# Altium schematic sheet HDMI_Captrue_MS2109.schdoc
size 297 x 209 mm; Border: 1; Symbol: Drawing-Symbol_A4; Company: 嘉立创EDA; Version: V1.0; Page Size: A4; @Project Name: New Project_2025-01-23_00-40-50; @Page Count: 4; @Update Date: 2025-08-15; @Create Date: 2025-07-30; @Schematic Name: Schematic3_7; @Page No: 4; @Page Name: 采集卡; @Create Time: 15:34:36; @Update Time: 14:29:42; Width: 1170; Height: 825; Region Start: 1; X Region Count: 6; Y Region Count: 4; Blade Width: 10; Title Block Position: 3; @Board Name: cm4; Device: Drawing-Symbol_A4
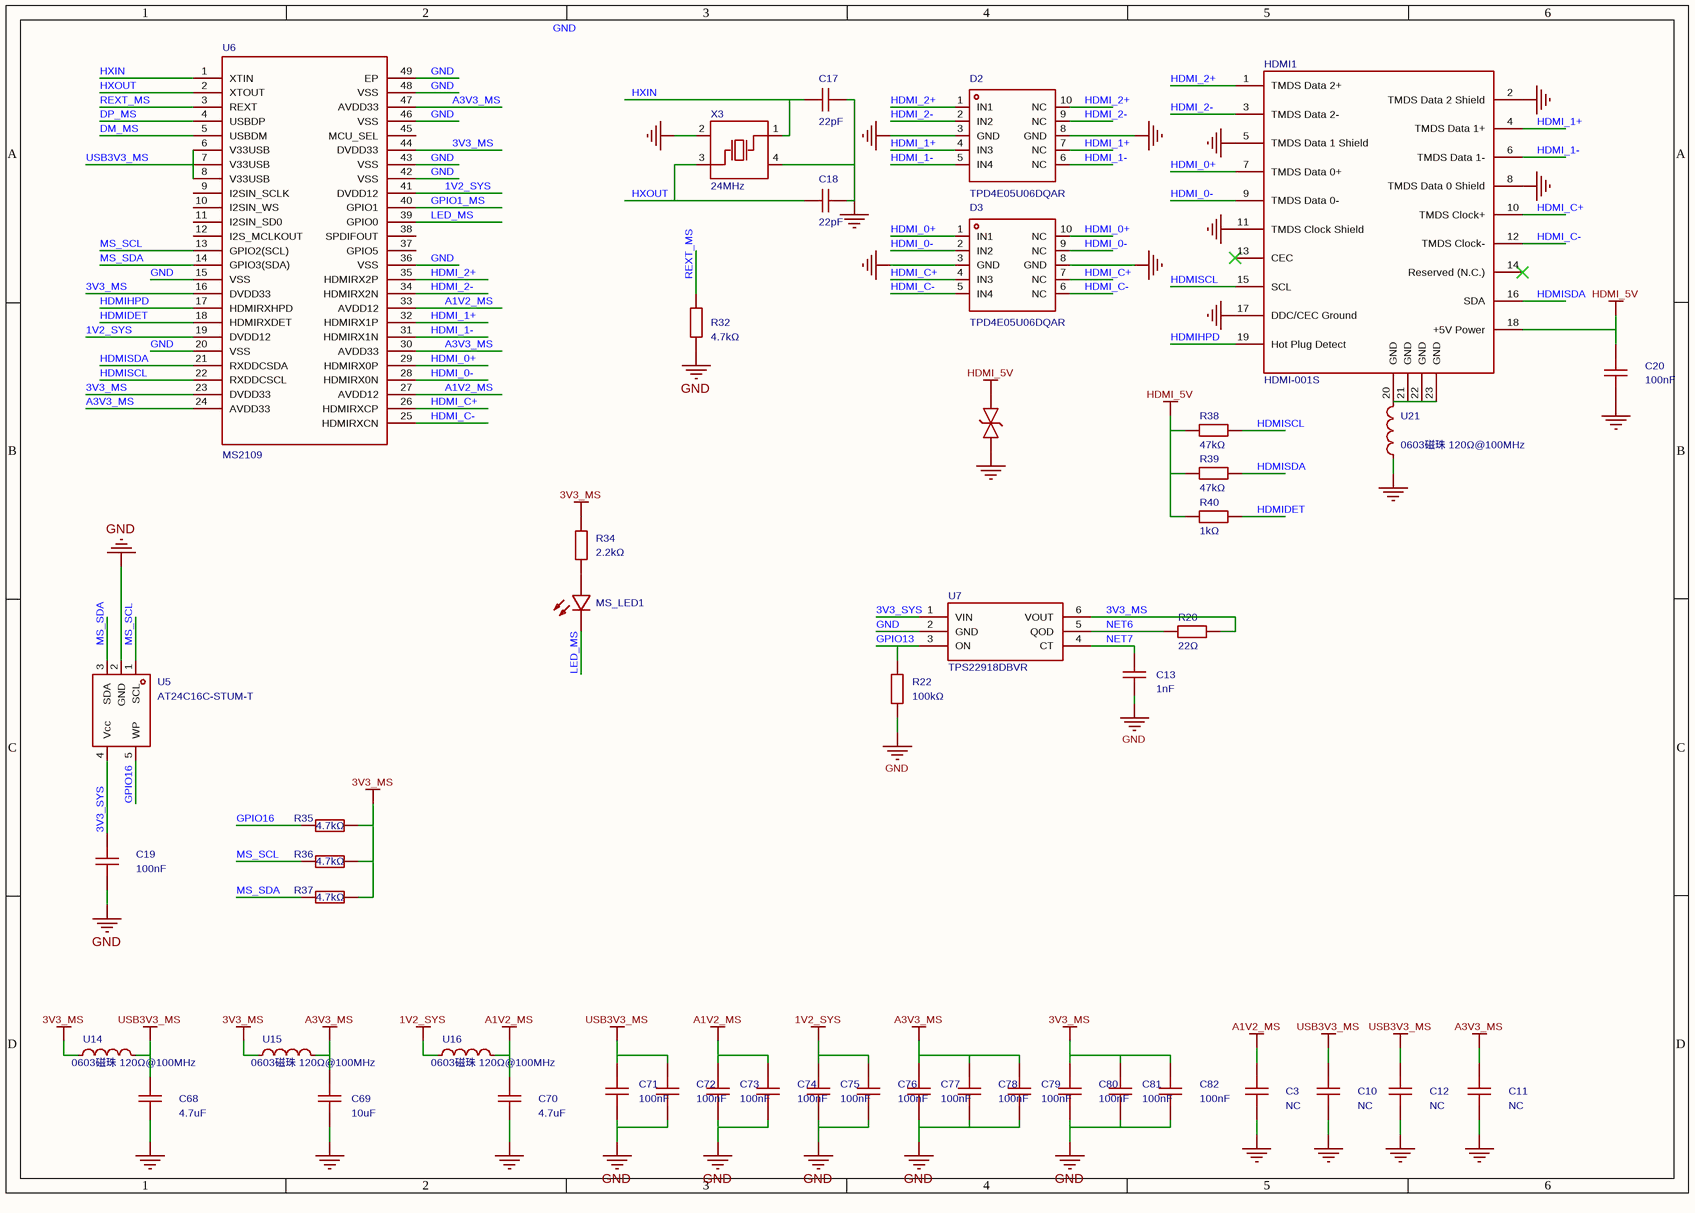
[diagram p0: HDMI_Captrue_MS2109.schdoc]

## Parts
C3  NC  [C0603]
C10  NC  [C0603]
C11  NC  [C0603]
C12  NC  [C0603]
C13  1nF  [C0402]
C17  22pF  [C0402]
C18  22pF  [C0402]
C19  100nF  [C0603]
C20  100nF  [C0603]
C68  4.7uF  [C0805]
C69  10uF  [C0805]
C70  4.7uF  [C0805]
C71  100nF  [C0402 去耦电容]
C72  100nF  [C0402 去耦电容]
C73  100nF  [C0402 去耦电容]
C74  100nF  [C0402 去耦电容]
C75  100nF  [C0402 去耦电容]
C76  100nF  [C0402 去耦电容]
C77  100nF  [C0402 去耦电容]
C78  100nF  [C0402 去耦电容]
C79  100nF  [C0402 去耦电容]
C80  100nF  [C0402 去耦电容]
C81  100nF  [C0402 去耦电容]
C82  100nF  [C0402 去耦电容]
D2  TPD4E05U06DQAR  [USON-10_L2.5-W1.0-P0.50-BL]
D3  TPD4E05U06DQAR  [USON-10_L2.5-W1.0-P0.50-BL]
D4  SLPESD0603M05  [D0603-BI]  (value not drawn)
HDMI1  HDMI-001S  [HDMI-SMD_HDMI-001S]
MS_LED1  NCD0603R1_C84263  [LED0603-RD_RED]  (value not drawn)
R20  22Ω  [R0402]
R22  100kΩ  [R0603]
R32  4.7kΩ  [R0603]
R34  2.2kΩ  [R0402]
R35  value 4.7kΩ  [R0603]  (hidden comment: 0603WAF4701T5E)
R36  value 4.7kΩ  [R0603]  (hidden comment: 0603WAF4701T5E)
R37  value 4.7kΩ  [R0603]  (hidden comment: 0603WAF4701T5E)
R38  47kΩ  [R0603]
R39  47kΩ  [R0603]
R40  1kΩ  [R0603]
U5  AT24C16C-STUM-T  [SOT-23-5_L2.9-W1.6-P0.95-LS2.8-BL]
U6  MS2109  [QFN-48_L7.0-W7.0-P0.50-TL-EP4.1]
U7  TPS22918DBVR  [SOT-23-6_L2.9-W1.6-P0.95-LS2.8-BR]
U14  LCSC Part Name: 0603磁珠 120Ω@100MHz  [L0603]  (hidden comment: BLM18PG121SN1D)
U15  LCSC Part Name: 0603磁珠 120Ω@100MHz  [L0603]  (hidden comment: BLM18PG121SN1D)
U16  LCSC Part Name: 0603磁珠 120Ω@100MHz  [L0603]  (hidden comment: BLM18PG121SN1D)
U21  LCSC Part Name: 0603磁珠 120Ω@100MHz  [L0603]  (hidden comment: BLM18PG121SN1D)
X3  24MHz  [CRYSTAL-SMD_4P-L3.2-W2.5-BL]

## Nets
1V2_SYS: C75.2 C76.2 U6.19(DVDD12) U6.41(DVDD12) U16.1
3V3_MS: C80.2 C81.2 C82.2 R20.2 R34.2 R35.2 R36.2 R37.2 U6.16(DVDD33) U6.23(DVDD33) U6.44(DVDD33) U7.6(VOUT) U14.1 U15.1
A1V2_MS: C3.2 C70.2 C73.2 C74.2 U6.27(AVDD12) U6.33(AVDD12) U16.2
A3V3_MS: C11.2 C69.2 C77.2 C78.2 C79.2 U6.24(AVDD33) U6.30(AVDD33) U6.47(AVDD33) U15.2
GND: C3.1 C10.1 C11.1 C12.1 C13.1 C17.2 C18.2 C19.1 C20.1 C68.1 C69.1 C70.1 C71.1 C72.1 C73.1 C74.1 C75.1 C76.1 C77.1 C78.1 C79.1 C80.1 C81.1 C82.1 D2.3(GND) D2.8(GND) D3.3(GND) D3.8(GND) D4.1 HDMI1.2(TMDS_Data_2_Shield) HDMI1.5(TMDS_Data_1_Shield) HDMI1.8(TMDS_Data_0_Shield) HDMI1.11(TMDS_Clock_Shield) HDMI1.17(DDC/CEC_Ground) R22.1 R32.1 U5.2(GND) U6.15(VSS) U6.20(VSS) U6.36(VSS) U6.42(VSS) U6.43(VSS) U6.46(VSS) U6.48(VSS) U6.49(EP) U7.2(GND) U21.1 X3.2(GND) X3.4(GND)
HDMI_5V: C20.2 D4.2 HDMI1.18(+5V_Power) R38.1 R39.1 R40.1
USB3V3_MS: C10.2 C12.2 C68.2 C71.2 C72.2 U6.6(V33USB) U6.7(V33USB) U6.8(V33USB) U14.2
3V3_SYS: C19.2 U5.4(Vcc) U7.1(VIN)
DM_MS: U6.5(USBDM)
DP_MS: U6.4(USBDP)
GPIO1_MS: U6.40(GPIO1)
GPIO13: R22.2 U7.3(ON)
GPIO16: R35.1 U5.5(WP)
HDMI_0+: D3.1(IN1) D3.10(NC) HDMI1.7(TMDS_Data_0+) U6.29(HDMIRX0P)
HDMI_0-: D3.2(IN2) D3.9(NC) HDMI1.9(TMDS_Data_0-) U6.28(HDMIRX0N)
HDMI_1+: D2.4(IN3) D2.7(NC) HDMI1.4(TMDS_Data_1+) U6.32(HDMIRX1P)
HDMI_1-: D2.5(IN4) D2.6(NC) HDMI1.6(TMDS_Data_1-) U6.31(HDMIRX1N)
HDMI_2+: D2.1(IN1) D2.10(NC) HDMI1.1(TMDS_Data_2+) U6.35(HDMIRX2P)
HDMI_2-: D2.2(IN2) D2.9(NC) HDMI1.3(TMDS_Data_2-) U6.34(HDMIRX2N)
HDMI_C+: D3.4(IN3) D3.7(NC) HDMI1.10(TMDS_Clock+) U6.26(HDMIRXCP)
HDMI_C-: D3.5(IN4) D3.6(NC) HDMI1.12(TMDS_Clock-) U6.25(HDMIRXCN)
HDMIDET: R40.2 U6.18(HDMIRXDET)
HDMIHPD: HDMI1.19(Hot_Plug_Detect) U6.17(HDMIRXHPD)
HDMISCL: HDMI1.15(SCL) R38.2 U6.22(RXDDCSCL)
HDMISDA: HDMI1.16(SDA) R39.2 U6.21(RXDDCSDA)
HXIN: C17.1 U6.1(XTIN) X3.1(OSC1)
HXOUT: C18.1 U6.2(XTOUT) X3.3(OSC2)
LED_MS: MS_LED1.1(K) U6.39(GPIO0)
MS_SCL: R36.1 U5.1(SCL) U6.13(GPIO2(SCL))
MS_SDA: R37.1 U5.3(SDA) U6.14(GPIO3(SDA))
NET6: R20.1 U7.5(QOD)
NET7: C13.2 U7.4(CT)
REXT_MS: R32.2 U6.3(REXT)
NetHDMI1_20: HDMI1.20(GND) HDMI1.21(GND) HDMI1.22(GND) HDMI1.23(GND) U21.2
NetMS_LED1_2: MS_LED1.2(A) R34.1

Not connected (* = marked no-connect by the designer): HDMI1 13(CEC)* 14(Reserved_(N.C.))*; U6 9(I2SIN_SCLK) 10(I2SIN_WS) 11(I2SIN_SD0) 12(I2S_MCLKOUT) 37(GPIO5) 38(SPDIFOUT) 45(MCU_SEL)

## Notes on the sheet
- Labels drawn without touching a wire or pin: GND

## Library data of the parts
C3 C10-C12 = CL10A105KB8NNNC: 容值:1uF;精度:±10%;额定电压:50V;温度系数:X5R;; Manufacturer: SAMSUNG(三星); Check: false; Add into BOM: yes; 3D Model: ac125912035d415993ca9572d50418b1; 3D Model Transform: 62.992,31.496,0,0,0,0,0,0,0; Tolerance: ±10%; Temperature Coefficient: X5R; Voltage Rating: 50V; ModelName: C0603_L1.6-W0.8-H0.8
C13 = 0402B102K500NT: 容值:1nF;精度:±10%;额定电压:50V;温度系数:X7R;; Manufacturer: FH(风华); Add into BOM: yes; Voltage Rating: 50V; Tolerance: ±10%; Temperature Coefficient: X7R; 3D Model: 36a51122f27c49738f86b3bfa98863e0; 3D Model Transform: 39.37,19.685,0,0,0,0,0,0,0; ModelName: C0402_L1.0-W0.5-H0.5
C17 C18 = 0402CG220J500NT: 容值:22pF;精度:±5%;额定电压:50V;温度系数:C0G;; Manufacturer: FH(风华); Add into BOM: yes; Tolerance: ±5%; Temperature Coefficient: C0G; 3D Model: 36a51122f27c49738f86b3bfa98863e0; 3D Model Transform: 39.37,19.685,0,0,0,0,0,0,0; Voltage Rating: 50V; ModelName: C0402_L1.0-W0.5-H0.5
C19 = CC0603KRX7R9BB104: 容值:100nF;精度:±10%;额定电压:50V;温度系数:X7R;; Manufacturer: YAGEO(国巨); Add into BOM: yes; Voltage Rating: 50V; Tolerance: ±10%; Temperature Coefficient: X7R; 3D Model: ac125912035d415993ca9572d50418b1; 3D Model Transform: 62.992,31.496,0,0,0,0,0,0,0; ModelName: C0603_L1.6-W0.8-H0.8
C20 = CC0603KRX7R9BB104: 容值:100nF;精度:±10%;额定电压:50V;温度系数:X7R;; Manufacturer: YAGEO(国巨); Add into BOM: yes; Voltage Rating: 50V; 3D Model: ac125912035d415993ca9572d50418b1; 3D Model Transform: 62.992,31.496,0,0,0,0,0,0,0; Tolerance: ±10%; Temperature Coefficient: X7R; ModelName: C0603_L1.6-W0.8-H0.8
C68 C70 = CL21A475KAQNNNE: 容值:4.7uF;精度:±10%;额定电压:25V;温度系数:X5R;; Manufacturer: SAMSUNG(三星); Add into BOM: yes; 3D Model: 1ba041120af144c991958decab20d241; 3D Model Transform: 78.74,51.181,0,0,0,0,0,0.0005,0; Tolerance: ±10%; Temperature Coefficient: X5R; Voltage Rating: 25V; ModelName: C0805_L2.0-W1.3-H1.3
C69 = CL21A106KAYNNNE_C15850: 容值:10uF;精度:±10%;额定电压:25V;温度系数:X5R;; Manufacturer: SAMSUNG(三星); Add into BOM: yes; 3D Model: 1ba041120af144c991958decab20d241; 3D Model Transform: 78.74,51.181,0,0,0,0,0,0.0005,0; Tolerance: ±10%; Temperature Coefficient: X5R; Voltage Rating: 25V; ModelName: C0805_L2.0-W1.3-H1.3
C71-C82 = CL05B104KO5NNNC: 容值:100nF;精度:±10%;额定电压:16V;温度系数:X7R;; Manufacturer: SAMSUNG(三星); Symbol: CC0603KRX7R9BB104; Check: false; Add into BOM: yes; Voltage Rating: 16V; Tolerance: ±10%; Temperature Coefficient: X7R; 3D Model: ac125912035d415993ca9572d50418b1; 3D Model Transform: 39.37,19.685,0,0,0,0,0,0,0; ModelName: C0402_L1.0-W0.5-H0.5
D2 D3 = TPD4E05U06DQAR_C138714: 极性:单向;反向截止电压(Vrwm):5.5V;最大钳位电压:14V;峰值脉冲电流(Ipp)@10/1000us:2.5A;峰值脉冲功率(Ppp)@10/1000us:40W;击穿电压:6V;; Manufacturer: TI(德州仪器); Symbol: RClamp0524PATCT; AddInBom: yes; ModelId: ab22a3507c584f4790945dcc3c1a797e; ModelName: USON-10_L2.5-W1.0-H0.6-P0.50; ModelTransform: 40.1574,98.425,0,90,0,0,0.001,0,0; polarity: 单向; Reverse Stand-Off Voltage (Vrwm): 5.5V; Maximum Clamping Voltage: 14V; Peak Pulse Current (Ipp)@10/1000us: 2.5A; Peak Pulse Power Dissipation (Ppp)@10/1000us: 40W; Breakdown Voltage: 6V; Number of Lines: 四路; Type: ESD
D4 = SLPESD0603M05: 极性:双向;反向截止电压(Vrwm):5V;钳位电压:40V;; Manufacturer: Slkor(萨科微); Add into BOM: yes; 3D Model: a387ce2936f842ebafc868b09fdf8ecc; 3D Model Transform: 62.992,31.496,0,0,0,0,0,0,0; Polarity: 双向; Reverse Stand-Off Voltage (Vrwm): 5V; Clamping Voltage: 40V; Reverse Leakage Current (Ir): 10nA; Number of Channels: 单路; Type: ESD; Junction Capacitance: 0.05pF; ModelName: DO0603_L1.6-W0.8-H0.8-LS1.6
HDMI1 = HDMI-001S: 19PIN A型前插后贴HDMI插座 铜壳; Manufacturer: XUNPU(讯普); AddInBom: yes; ModelId: a430605dedcd475db3c10e0e5e336730; ModelTransform: 590.5878,468.503,0,0,0,0,0,-79.567,-85.039; Connector Type: HDMI-A; Gender: 母
MS_LED1 = NCD0603R1_C84263: 灯头类型:-;发光颜色:红色;正向压降(Vf):1.6V~2.6V;功率:65mW;正向电流:25mA;波长:615nm~630nm;二极管配置:独立二极管;透镜颜色:-;色温:-;发光强度:80mcd~220mcd;发光角度:130°;载带方式:-;工作温度:-30℃~+85℃;; Manufacturer: 国星光电; Symbol: FC-DA1608HRK-620D; AddInBom: yes; ModelId: 74041d3a270d435c8600a9ab9b7641c0; ModelTransform: 63.7794,31.496,0,0,0,0,0,0,0; Illumination Color: 红色; Power(Watts): 65mW; Forward Current: 25mA; Diode Configuration: 独立二极管; Viewing Angle: 130°
R20 = 0402WGF220JTCE: 电阻类型:厚膜电阻;阻值:22Ω;精度:±1%;功率:62.5mW;最大工作电压:50V;温度系数:±100ppm/℃;; Manufacturer: UNI-ROYAL(厚声); Add into BOM: yes; 3D Model: 98c88bc2b9094f218f3a3e30a7012738; 3D Model Transform: 39.37,19.685,0,0,0,0,0,0,0; Tolerance: ±1%; Power(Watts): 62.5mW; Overload Voltage (Max): 50V; ModelName: R0402_L1.0-W0.5-H0.4
R22 = 0603WAF1003T5E: 电阻类型:厚膜电阻;阻值:100kΩ;精度:±1%;功率:100mW;工作电压:75V;温度系数:±100ppm/℃;; Manufacturer: UNI-ROYAL(厚声); Add into BOM: yes; 3D Model: fc143cca1e79419f9cd78b61e9279f08; 3D Model Transform: 31.8897,63.7794,0,90,0,0,0,0,0; Tolerance: ±1%; Power(Watts): 100mW; Voltage-Supply(Max): 75V
R32 = 0603WAF4701T5E: 电阻类型:厚膜电阻;阻值:4.7kΩ;精度:±1%;功率:100mW;工作电压:75V;温度系数:±100ppm/℃;; Manufacturer: UNI-ROYAL(厚声); Add into BOM: yes; Tolerance: ±1%; Power(Watts): 100mW; 3D Model: fc143cca1e79419f9cd78b61e9279f08; 3D Model Transform: 31.8897,63.7794,0,90,0,0,0,0,0; Voltage-Supply(Max): 75V
R34 = 0402WGF2201TCE: 电阻类型:厚膜电阻;阻值:2.2kΩ;精度:±1%;功率:62.5mW;工作电压:50V;温度系数:±100ppm/℃;; Manufacturer: UNI-ROYAL(厚声); Add into BOM: yes; Tolerance: ±1%; Power(Watts): 62.5mW; 3D Model: 98c88bc2b9094f218f3a3e30a7012738; 3D Model Transform: 39.37,19.685,0,0,0,0,0,0,0; Voltage-Supply(Max): 50V; ModelName: R0402_L1.0-W0.5-H0.4
R35-R37 = 0603WAF4701T5E: 电阻类型:厚膜电阻;阻值:4.7kΩ;精度:±1%;功率:100mW;最大工作电压:75V;温度系数:±100ppm/℃;; Manufacturer: UNI-ROYAL(厚声); Symbol: 0402WGF4701TCE; Tolerance: ±1%; Power(Watts): 100mW; AddInBom: yes; ModelId: fc143cca1e79419f9cd78b61e9279f08; ModelTransform: 31.8897,63.7794,0,90,0,0,0,0,0; Overload Voltage (Max): 75V
R38 R39 = 0603WAF4702T5E: 电阻类型:厚膜电阻;阻值:47kΩ;精度:±1%;功率:100mW;工作电压:75V;温度系数:±100ppm/℃;; Manufacturer: UNI-ROYAL(厚声); Add into BOM: yes; Tolerance: ±1%; Power(Watts): 100mW; 3D Model: fc143cca1e79419f9cd78b61e9279f08; 3D Model Transform: 31.8897,63.7794,0,90,0,0,0,0,0; Voltage-Supply(Max): 75V
R40 = 0603WAF1001T5E: 电阻类型:厚膜电阻;阻值:1kΩ;精度:±1%;功率:100mW;最大工作电压:75V;温度系数:±100ppm/℃;; Manufacturer: UNI-ROYAL(厚声); Symbol: 0402WGF1001TCE; Tolerance: ±1%; Power(Watts): 100mW; Overload Voltage (Max): 75V; 3D Model: fc143cca1e79419f9cd78b61e9279f08; 3D Model Transform: 31.8897,63.7794,0,90,0,0,0,0,0; AddInBom: yes
U5 = AT24C16C-STUM-T: 接口类型:I2C;存储容量:16Kbit;时钟频率(fc):1MHz;; Manufacturer: MICROCHIP(美国微芯); AddInBom: yes; ModelId: 018c57e721114987ae90467fe9f1d2590819f05c4eef4c71ace90d822a990e87; ModelTransform: 114.96,110.236,0,0,0,0,0,0,0; Interface: I2C; Memory Size: 16Kbit; Clock Frequency: 1MHz; Write Cycle Time(Tw): 5ms; Data Retention - TDR (Year): 100年; Write Cycle Endurance: 100万次; Voltage - Supply: 1.7V~5.5V
U6 = MS2109: Check: false; Add into BOM: yes; Origin Footprint: QFN48-7X7X05P
U7 = TPS22918DBVR: 类型:负载开关;通道数:1;输入控制逻辑:高电平有效;工作电压:1V~5.5V;最大连续电流:2A;导通电阻:53mΩ;; Manufacturer: TI(德州仪器); AddInBom: yes; ModelId: 18da8f6c14a34920b3e136b5c401a1190819f05c4eef4c71ace90d822a990e87; ModelName: SOT-23-6_L2.9-W1.6-H1.5-LS2.8-P0.95; ModelTransform: 110.73671,114.173,0,180,0,0,0.001,-0.003,0; Number of Channels: 1; Control Input Logic: 高电平有效; Maximum Continuous Current: 2A; RDS(on): 53mΩ
U14 = BLM18PG121SN1D: 标称阻抗@测试频率:120Ω@100MHz;误差:±25%;直流电阻(RDC):50mΩ;; Manufacturer: muRata(村田); Symbol: BLM18PG121SN1D_C14709; AddInBom: yes; ModelId: 2bc5ec593d464d6ba9807aec0b5673c2; ModelName: L0603_L1.6-W0.8-H0.5_BEAD; ModelTransform: 62.992,31.496,0,180,0,0,0.094,0.629,0; Tolerance: ±25%; DC Resistance: 50mΩ; Current Rating: 2A; Circuits: 1
U15 U16 U21 = BLM18PG121SN1D: 标称阻抗@测试频率:120Ω@100MHz;误差:±25%;直流电阻(RDC):50mΩ;; Manufacturer: muRata(村田); Symbol: BLM18PG121SN1D_C14709; 3D Model: 2bc5ec593d464d6ba9807aec0b5673c2; 3D Model Transform: 62.992,31.496,0,180,0,0,0.094,0.629,0; Tolerance: ±25%; DC Resistance: 50mΩ; Current Rating: 2A; Circuits: 1; AddInBom: yes; ModelName: L0603_L1.6-W0.8-H0.5_BEAD
X3 = X322524MOB4SI: 晶振类型:贴片晶振;频率:24MHz;常温频差:±10ppm;负载电容:12pF;频率稳定度:±20ppm;; Manufacturer: YXC(扬兴晶振); Add into BOM: yes; 3D Model: ff2dfd5650294453a14147960efe1838; 3D Model Transform: 125.984,98.425,0,0,0,0,0,0,0; Normal temperature Frequency Tolerance: ±10ppm; Load Capacitance: 12pF; Frequency Stability: ±20ppm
